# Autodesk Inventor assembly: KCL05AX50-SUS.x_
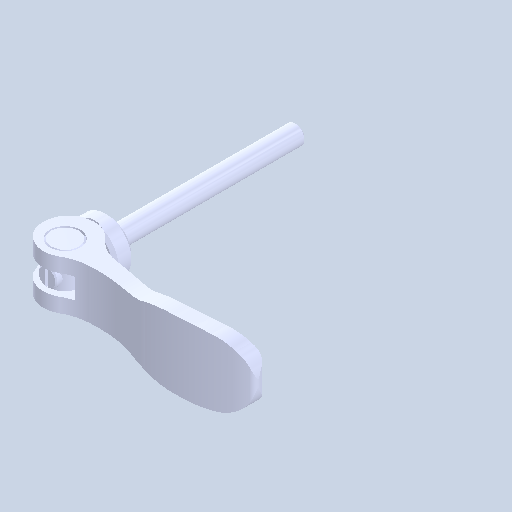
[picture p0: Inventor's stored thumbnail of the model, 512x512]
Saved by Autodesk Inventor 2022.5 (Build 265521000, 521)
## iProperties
Created: 2024-08
Part Number: KCL05AX50-SUS.x_
Document SubType Name: Assembly
Designer: ImaoCorp
Author: ImaoCorp
Sending System: SOLIDWORKS 2022-2022290
MC: AMD64
MC_MODEL: Intel64 Family 6 Model 60 Stepping 3, GenuineIntel
OS: Windows_NT
FRU: Parasolid Version 33.1, build 260,  4-25-2022
FORMAT: text
GUISE: transmit
KEY: FILEKCL05AX50-SUS.x_t
DATE: Thu Aug 29 10:48:53 2024
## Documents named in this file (5)
- Y:\5.更新分\2024年対応\1001_KCL\データ\kcl05ax50-sus\KCL05AX50-SUS.x_.iam
- Y:\5.更新分\2024年対応\1001_KCL\データ\kcl05ax50-sus\KCL05AX50-SUS_01.ipt
- Y:\5.更新分\2024年対応\1001_KCL\データ\kcl05ax50-sus\KCL05AX50-SUS_02.ipt
- Y:\5.更新分\2024年対応\1001_KCL\データ\kcl05ax50-sus\KCL05AX50-SUS_03.ipt
- Y:\5.更新分\2024年対応\1001_KCL\データ\kcl05ax50-sus\KCL05AX50-SUS_04.ipt
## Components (4 placed, 4 different names)
1. KCL05AX50-SUS_01
2. KCL05AX50-SUS_02
3. KCL05AX50-SUS_03
4. KCL05AX50-SUS_04
